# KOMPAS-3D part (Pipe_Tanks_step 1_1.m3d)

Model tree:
1. X Axis
2. Y Axis
3. Z Axis  (labels: Pipe Dn 50; Bend 90 Dn 50; C:\Program Files\ASCON\KOMPAS-3D V10\Sys\graphic.lyt; Pipe_Tanks_step 1_1.m3d)
     Òîëùèíà ñòåíêè 1 = 1

Referenced files in C:\Documents and Settings\kashirsky\Мои документы\Camtasia Studio\Pipelines3D\Tanks\: Tanks_step 1.a3d, Tanks_step 1.spw
Referenced files in C:\Documents and Settings\kashirsky\Мои документы\Camtasia Studio\Pipelines3D\Tanks\Tanks_step 1_Pipes\: Pipe_Tanks_step 1_1.m3d
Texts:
  Pipe Dn 50
  Steel ASTM A295
  Three Point Plane
  Plane at Angle
  Line and Point Plane
  Axis through Two Vertices
  Axis of Feature
  Axis of Conical Surface
  Axis through Edge
  Trim by Surface
  Trim by Sketch
  Feature with No History
  Intersection Axis of Two Planes
  Two Line Plane
  Line and Face Plane
  Bend by line
  Hole in sheet body
  Cut in sheet body
  Point in CM
  Linear Dimension from Line to Point
  Surface Finish Symbol
  Geometric Tolerance Symbol
  Leader #1
  Leader #2
  Leader #3
  Shape Deviations and Datum
  Node point number
  Mark of coordination axis
  Node point designation
  Mark/Reference designation with leader
  Mark/reference designation on line
  Mark/Reference designation without leader
  Bend 90 Dn 50
  Plane of section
